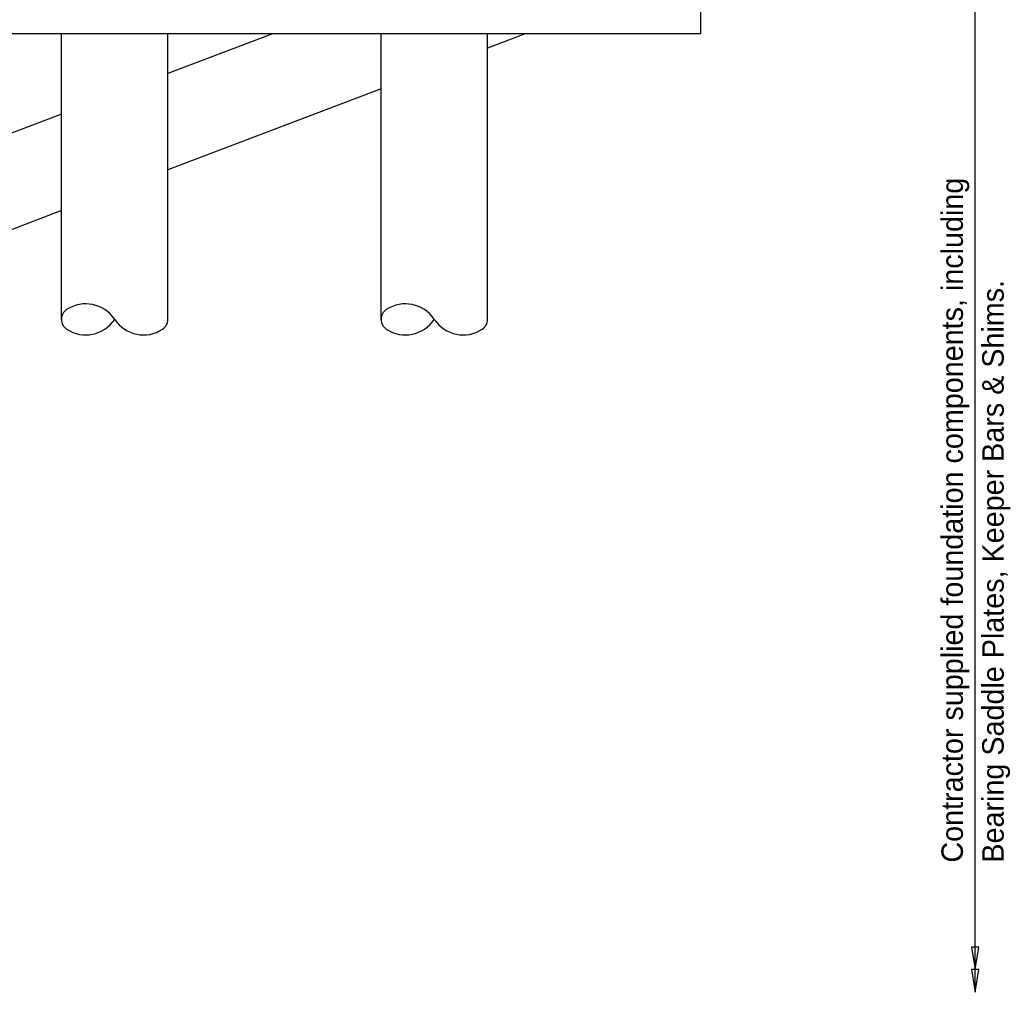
# Model space of a CAD drawing. Extents: x -4.4 to 30.2, y 1.2 to 17.8.
# Drawn here: x 22.97 to 29.95, y 1.23 to 8.08 of the extents above; entities that cross this region are included whole.
import ezdxf

# ---------------------------------------------------------------- set-up
doc = ezdxf.new("R2010")
doc.units = 0
for name, color, linetype in [('Dimension', 7, 'Continuous'), ('TextStructures', 7, 'Continuous'), ('Wood', 7, 'Continuous')]:
    doc.layers.add(name, color=color, linetype=linetype)

msp = doc.modelspace()

# ---------------------------------------------------------------- linework, layer by layer
at = {"layer": 'Dimension'}
msp.add_line((29.6984, 1.2313), (29.6984, 15.2902), dxfattribs=at)
for points in [[(29.6984, 1.3902), (29.7249, 1.5491), (29.672, 1.5491)], [(29.6984, 1.2313), (29.7249, 1.3902), (29.672, 1.3902)]]:
    msp.add_lwpolyline(points, close=True, dxfattribs=at)
at = {"layer": 'Wood'}
for p, q in [((27.7658, 7.9821), (27.7658, 8.7452)), ((27.7658, 7.9821), (15.4567, 7.9821)), ((23.264, 5.9699), (23.264, 7.9821)), ((24.7496, 7.9821), (24.0143, 7.7016)), ((24.0143, 5.9699), (24.0143, 7.9821)), ((25.5149, 5.9699), (25.5149, 7.9821)), ((26.5303, 7.9821), (26.2652, 7.881)), ((26.2652, 5.9699), (26.2652, 7.9821)), ((25.5149, 7.5948), (24.0143, 7.0225)), ((23.264, 7.4155), (20.4632, 6.3472)), ((23.264, 6.7363), (22.2438, 6.3472))]:
    msp.add_line(p, q, dxfattribs=at)
for centre, major_axis, start_param, end_param in [((23.4356, 5.8284), (0, 0.251), 5.311474, 6.859887), ((25.6865, 5.8284), (0, 0.251), 5.311474, 6.859887), ((23.3443, 5.9699), (0, 0.0817), 0.569243, 1.570759), ((25.5952, 5.9699), (0, 0.0817), 0.569243, 1.570759), ((23.3443, 5.9699), (0, 0.0817), 1.570759, 2.57235), ((23.4356, 6.1114), (0, 0.251), 2.564849, 4.113262), ((23.8429, 6.1113), (0, -0.2507), 5.311304, 6.859717), ((23.934, 5.9699), (0, 0.0817), 3.710836, 4.712426), ((25.5952, 5.9699), (0, 0.0817), 1.570759, 2.57235), ((25.6865, 6.1114), (0, 0.251), 2.564849, 4.113262), ((26.0938, 6.1113), (0, -0.2507), 5.311304, 6.859717), ((26.1848, 5.9699), (0, 0.0817), 3.710836, 4.712426)]:
    msp.add_ellipse(centre, major_axis=major_axis, ratio=0.983193, start_param=start_param, end_param=end_param, dxfattribs=at)

# ---------------------------------------------------------------- texts
at = {"layer": 'TextStructures'}
for s, p in [('Contractor supplied foundation components, including ', (29.6123, 2.144)), ('Bearing Saddle Plates, Keeper Bars & Shims.', (29.8997, 2.144))]:
    msp.add_text(s, height=0.15126, rotation=90, dxfattribs=at).set_placement(p)

doc.saveas('drawing.dxf')
